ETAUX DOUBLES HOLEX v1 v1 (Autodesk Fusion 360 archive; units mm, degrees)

design "ETAUX DOUBLES HOLEX v1"
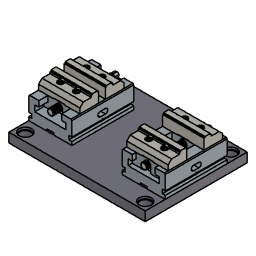
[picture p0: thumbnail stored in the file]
description: Part Number
part number: 1-lisse 2-lisse
part number: BASE (1)
part number: MORS 2 (1)
part number: MORS 1 (1)
part number: VIS (1)
part number: PIVOT (1)
part number: 150208: 150205 (2)
part number: 150208: D912_M10X30-10_9 (3)
part number: 150208: D912_M10X30-10_9 (1) (2)
part number: CAD_363312_120 (2)
part number: mors lisses v2 (2)
part number: 150208: 150205 (3)
part number: 150208: D912_M10X30-10_9 (4)
part number: 150208: D912_M10X30-10_9 (1) (3)
part number: CAD_363312_120 (3)
part number: mors lisses v2 (3)
part number: 150216: 150217 (2)
part number: 150216: D912_M10X30-10_9 (3)
part number: 150216: D912_M10X30-10_9 (1) (2)
parameter "Ouverture_etau_2" = 20
parameter "Ouverture_etau_1" = 50
base_feature "Base Feature1"
base_feature "Base Feature1"
base_feature "Base Feature1"
base_feature "Base Feature1"
base_feature "Base Feature1"
base_feature "Base Feature1"
base_feature "Base Feature1"
base_feature "Base Feature1"
base_feature "Base Feature1"
base_feature "Base Feature1"
base_feature "Base Feature1"
base_feature "Base Feature1"
base_feature "Base Feature1"
base_feature "Base Feature1"
base_feature "Base Feature1"
base_feature "Base Feature1"
base_feature "Base Feature1"
base_feature "Base Feature1"
base_feature "Base Feature1"
base_feature "Base Feature1"
base_feature "Base Feature1"
base_feature "Base Feature1"
base_feature "Base Feature1"
base_feature "Base Feature1"
base_feature "Base Feature1"
base_feature "Base Feature1"
base_feature "Base Feature1"
base_feature "Base Feature1"
base_feature "Base Feature1"
base_feature "Base Feature1"
base_feature "Base Feature1"
base_feature "Base Feature1"
base_feature "Base Feature1"
base_feature "Base Feature1"
base_feature "Base Feature1"
base_feature "Base Feature1"
base_feature "Base Feature1"
base_feature "Base Feature1"
base_feature "Base Feature1"
position "Position1"
ground "Fixer1"
ground "Fixer2"
ground "Fixer3"
ground "Fixer4"
ground "Fixer5"
ground "Fixer6"
ground "Fixer7"
as_built_joint "Réelle1"
as_built_joint "Réelle2"
work_plane "Plan de construction1"
work_plane "Plan de construction2"
position "Position2"
as_built_joint "Réelle3"
as_built_joint "Réelle4"
position "Position3"
joint "Assembler1" alignOffsetX 0 alignOffsetY 0 alignOffsetZ -10 (= "-Ouverture_etau_2 / 2")
joint "Assembler2" alignOffsetX 0 alignOffsetY 0 alignOffsetZ 10 (= "Ouverture_etau_2 / 2")
joint "Assembler1" alignOffsetX 0 alignOffsetY 0 alignOffsetZ -25 (= "-Ouverture_etau_1 / 2")
joint "Assembler2" alignOffsetX 0 alignOffsetY 0 alignOffsetZ 25 (= "Ouverture_etau_1 / 2")
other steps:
create_component "CreateComponent1"
create_component "CreateComponent1"
create_component "CreateComponent2"
create_component "CreateComponent3"
create_component "CreateComponent4"
create_component "CreateComponent5"
create_component "CreateComponent6"
create_component "CreateComponent1"
create_component "CreateComponent1"
create_component "CreateComponent2"
create_component "CreateComponent3"
create_component "CreateComponent7"
create_component "CreateComponent1"
create_component "CreateComponent1"
create_component "CreateComponent2"
create_component "CreateComponent3"
create_component "CreateComponent8"
create_component "CreateComponent1"
create_component "CreateComponent1"
create_component "CreateComponent2"
create_component "CreateComponent3"
create_component "CreateComponent9"
create_component "CreateComponent1"
create_component "CreateComponent1"
create_component "CreateComponent2"
create_component "CreateComponent3"
create_component "CreateComponent10"
create_component "CreateComponent11"
create_component "CreateComponent2"
create_component "CreateComponent3"
create_component "CreateComponent1"
create_component "CreateComponent2"
create_component "CreateComponent3"
create_component "CreateComponent4"
create_component "CreateComponent5"
create_component "CreateComponent6"
create_component "CreateComponent1"
create_component "CreateComponent1"
create_component "CreateComponent2"
create_component "CreateComponent3"
create_component "CreateComponent7"
create_component "CreateComponent1"
create_component "CreateComponent1"
create_component "CreateComponent2"
create_component "CreateComponent3"
create_component "CreateComponent8"
create_component "CreateComponent1"
create_component "CreateComponent1"
create_component "CreateComponent2"
create_component "CreateComponent3"
create_component "CreateComponent9"
create_component "CreateComponent1"
create_component "CreateComponent1"
create_component "CreateComponent2"
create_component "CreateComponent3"
create_component "CreateComponent10"
create_component "CreateComponent11"
joint_origin "JointOrigin1"
joint_origin "JointOrigin3"
joint_origin "JointOrigin3"
joint_origin "JointOrigin4"
joint_origin "JointOrigin1"
joint_origin "JointOrigin1"
joint_origin "JointOrigin1"
joint_origin "JointOrigin2"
